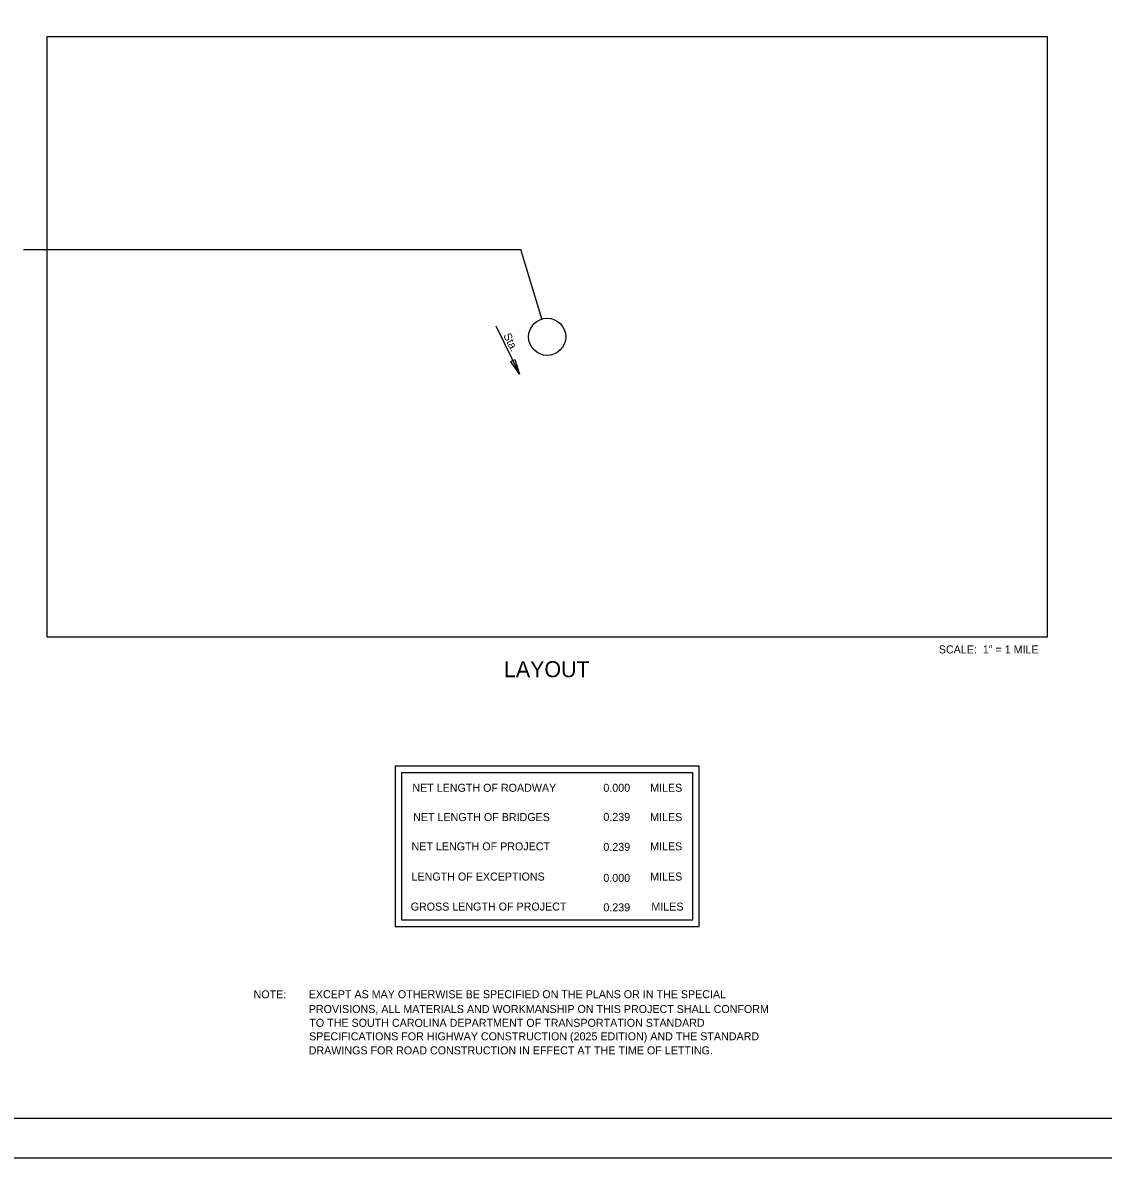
# Model space of a CAD drawing. Extents: x 291 to 2091, y 224 to 1324.
# Drawn here: x 892 to 1567, y 224 to 933 of the extents above; entities that cross this region are included whole.
import ezdxf

# ---------------------------------------------------------------- set-up
doc = ezdxf.new("R2010")
doc.units = 0
for name, color, linetype in [('BR_BORDER LINES', 7, 'Continuous'), ('BR_REBAR', 7, 'Continuous'), ('BR_TEXT', 7, 'Continuous'), ('Default', 7, 'Continuous'), ('RD_SHT_IplotShp', 7, 'Continuous')]:
    doc.layers.add(name, color=color, linetype=linetype)

msp = doc.modelspace()

# ---------------------------------------------------------------- linework, layer by layer
at = {"layer": 'BR_BORDER LINES'}
msp.add_line((391.1, 249.11), (2066.1, 249.11), dxfattribs=at)
at = {"layer": 'BR_REBAR'}
for p, q in [((906.87, 549.64), (906.87, 924.64)), ((906.87, 924.64), (1531.87, 924.64)), ((1531.87, 924.64), (1531.87, 549.64)), ((892.13, 791.71), (1202.92, 791.71)), ((1216.01, 748.27), (1202.92, 791.71)), ((1187.31, 743.95), (1202.14, 713.9)), ((1531.87, 549.64), (906.87, 549.64))]:
    msp.add_line(p, q, dxfattribs=at)
msp.add_lwpolyline([(1199.25, 722.93), (1202.14, 713.9), (1196.73, 721.68)], close=True, dxfattribs=at)
msp.add_circle((1219.37, 737.14), 11.62, dxfattribs=at)
at = {"layer": 'BR_TEXT'}
for points in [[(1314.37, 468.89), (1124.37, 468.89), (1124.37, 368.89), (1314.37, 368.89)], [(1310.37, 464.89), (1128.37, 464.89), (1128.37, 372.89), (1310.37, 372.89)]]:
    msp.add_lwpolyline(points, close=True, dxfattribs=at)
at = {"layer": 'Default'}
for p, q in [((906.87, 549.64), (906.87, 924.64)), ((906.87, 924.64), (1531.87, 924.64)), ((1531.87, 924.64), (1531.87, 549.64)), ((1531.87, 549.64), (906.87, 549.64))]:
    msp.add_line(p, q, dxfattribs=at)
at = {"layer": 'RD_SHT_IplotShp'}
msp.add_lwpolyline([(291.1, 1324.04), (2091.1, 1324.04), (2091.1, 224.04), (291.1, 224.04)], close=True, dxfattribs=at)

# ---------------------------------------------------------------- texts
at = {"layer": 'BR_REBAR'}
msp.add_text('Sta.', height=5, rotation=296.26167, dxfattribs=at).set_placement((1191.82, 738.05))
at = {"layer": 'BR_TEXT'}
for s, height, p in [('SCALE:  1" = 1 MILE', 5, (1464.11, 539.38)), ('LAYOUT', 10, (1192.37, 524.54)), ('NET LENGTH OF ROADWAY', 5, (1135.12, 452.97)), ('0.000', 5, (1254.49, 452.97)), ('MILES', 5, (1283.73, 452.97)), ('0.239', 5, (1254.49, 434.79)), ('NET LENGTH OF BRIDGES', 5, (1135.62, 434.67)), ('MILES', 5, (1283.72, 434.67)), ('NET LENGTH OF PROJECT', 5, (1134.62, 416.37)), ('0.239', 5, (1254.49, 416.06)), ('MILES', 5, (1283.72, 416.37)), ('LENGTH OF EXCEPTIONS', 5, (1134.62, 397.52)), ('0.000', 5, (1254.49, 396.69)), ('MILES', 5, (1283.74, 397.52)), ('GROSS LENGTH OF PROJECT', 5, (1134.07, 378.77)), ('0.239', 5, (1254.49, 378.28)), ('MILES', 5, (1284.49, 378.77)), ('NOTE:', 5, (1035.88, 323.96)), ('EXCEPT AS MAY OTHERWISE BE SPECIFIED ON THE PLANS OR IN THE SPECIAL ', 5.0001, (1070.33, 324.02)), ('PROVISIONS, ALL MATERIALS AND WORKMANSHIP ON THIS PROJECT SHALL CONFORM ', 5.0001, (1070.38, 314.77)), ('TO THE SOUTH CAROLINA DEPARTMENT OF TRANSPORTATION STANDARD ', 5.0001, (1070.74, 306.16)), ('SPECIFICATIONS FOR HIGHWAY CONSTRUCTION (2025 EDITION) AND THE STANDARD', 5.0001, (1070.59, 297.73)), ('DRAWINGS FOR ROAD CONSTRUCTION IN EFFECT AT THE TIME OF LETTING.', 5.0001, (1070.36, 288.95))]:
    msp.add_text(s, height=height, dxfattribs=at).set_placement(p)

doc.saveas('drawing.dxf')
